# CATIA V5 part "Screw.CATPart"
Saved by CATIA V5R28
Part number: Screw
Material "Grey": density 7860 kg/m3, Young's modulus 2e+11 Pa, Poisson ratio 0.266
Bounding box of the stored display mesh (mm): x -6.5 to 6.5, y -6.49 to 6.49, z 0 to 40
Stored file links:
  C:\Users\Parisa\Desktop\tarah sanat\Oldham Coupling\Screw.CATPart
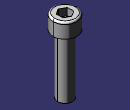
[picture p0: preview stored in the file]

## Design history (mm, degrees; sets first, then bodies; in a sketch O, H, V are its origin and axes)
Body1 (main body), material "Grey"
  Sketch1 on xy-plane, origin (0, 0, 0), H (1, 0, 0), V (0, 1, 0)
    circle A1 centre (0, 0) radius 4
    radius A1 = 4
  Pad1: profile Sketch1, direction (0, 0, 1), length 32
  Sketch2 on end face of Pad1, origin (0, 0, 32), H (1, 0, 0), V (0, 1, 0)
    circle A1 centre (0, 0) radius 6.5
    radius A1 = 6.5
  Pad2: profile Sketch2, direction (0, 0, 1), length 8
  Sketch3 on end face of Pad2, origin (0, 0, 40), H (1, 0, 0), V (0, 1, 0)
    point P1 (1.5231, 2.6655)
    construction circle A1 centre (0, 0) radius 3.5449
    construction circle A2 centre (0, 0) radius 3.07
    point P2 (3.0621, 1.7861)
    point P3 (-0.0158, 3.5449)
    point P4 (-3.0779, 1.7588)
    point P5 (-3.0621, -1.7861)
    point P6 (0.0158, -3.5449)
    point P7 (3.0779, -1.7588)
    line L1 (3.0621, 1.7861) -> (-0.0158, 3.5449)
    line L2 (-0.0158, 3.5449) -> (-3.0779, 1.7588)
    line L3 (-3.0779, 1.7588) -> (-3.0621, -1.7861)
    line L4 (-3.0621, -1.7861) -> (0.0158, -3.5449)
    line L5 (0.0158, -3.5449) -> (3.0779, -1.7588)
    line L6 (3.0779, -1.7588) -> (3.0621, 1.7861)
    construction line L7 (0, 0) -> (1.5231, 2.6655)
    distance L3 L6 = 6.14
    coincidence: A1 P2, A1 P3, A1 P4, A1 P5, A1 P6, A1 P7
    tangency: A2 L1, A2 L2, A2 L3, A2 L4, A2 L5, A2 L6
    midpoint: P1 L1
  Pocket1: profile Sketch3, direction (0, 0, -1), length 4
  Fillet1: radius 1, on edge [face of Pad2 from Sketch2.A1 | end face of Pad2]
